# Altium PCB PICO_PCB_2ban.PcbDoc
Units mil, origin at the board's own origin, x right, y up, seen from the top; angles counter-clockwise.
Board outline 6000 x 4000 mil, 2 copper layers (Top Layer, Bottom Layer); 2 components, 20 nets, 86 pads, 1 vias.
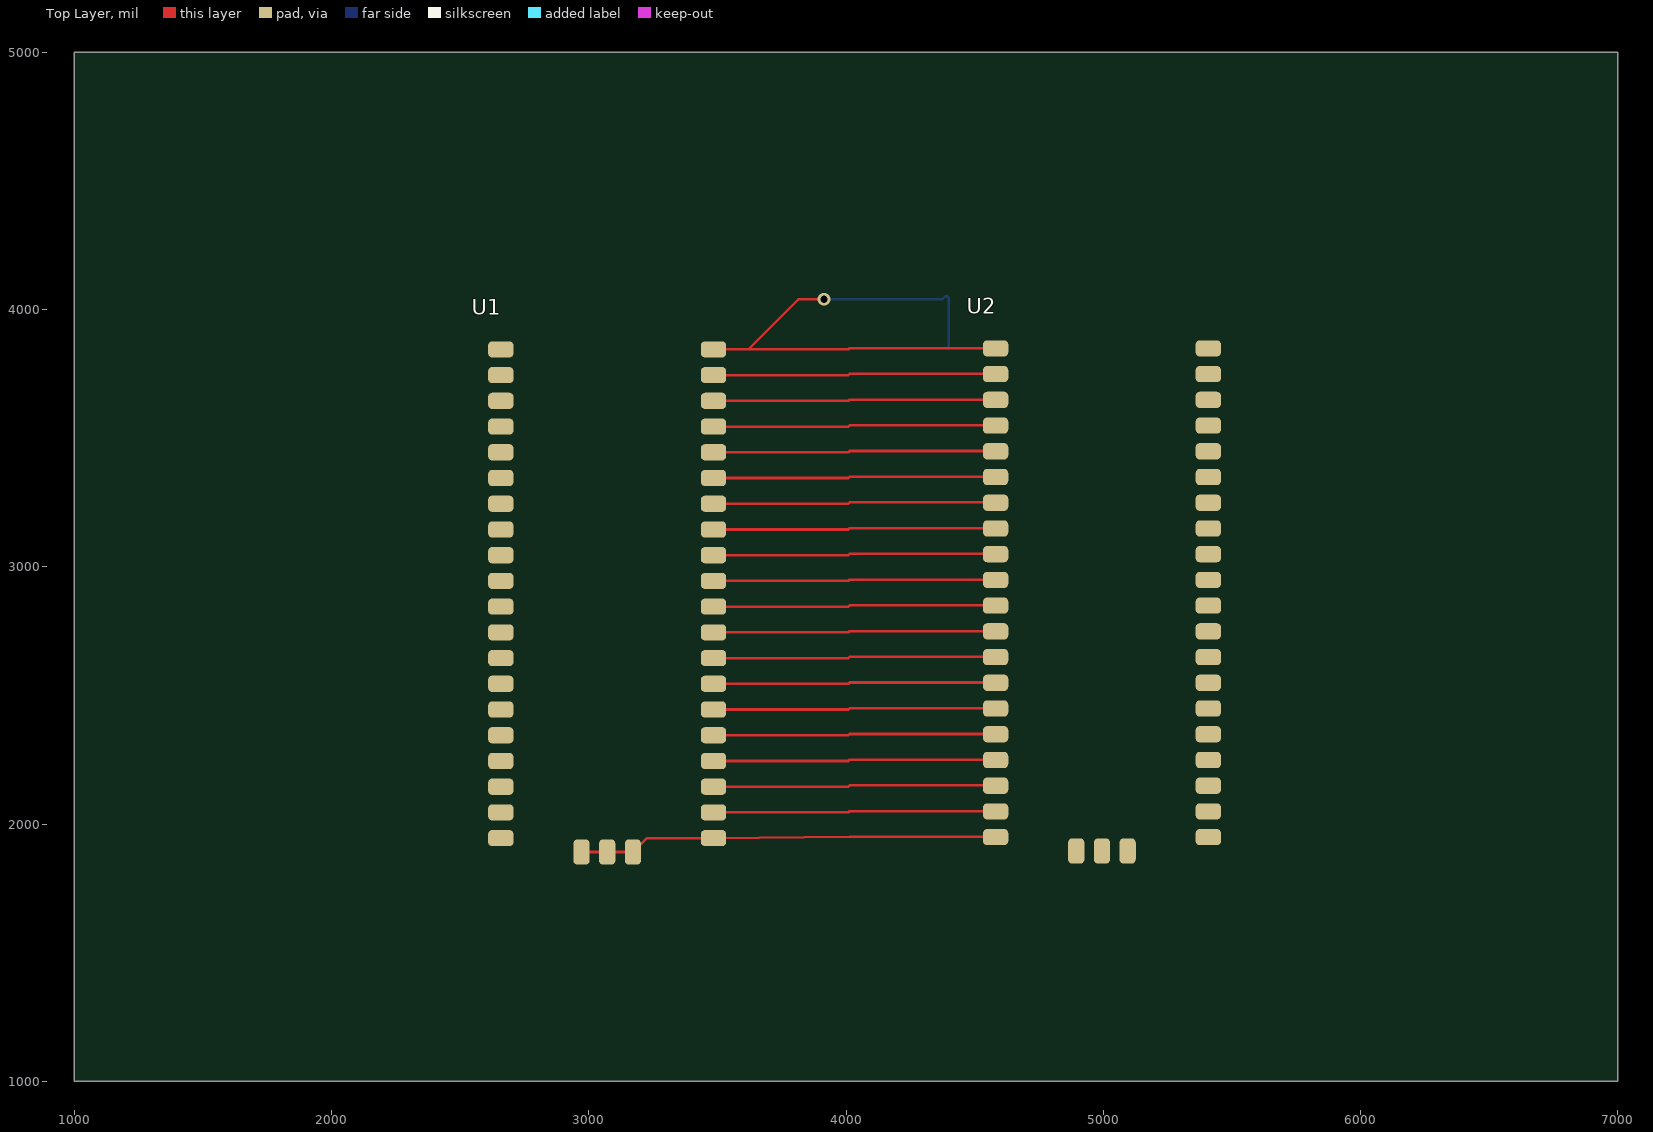
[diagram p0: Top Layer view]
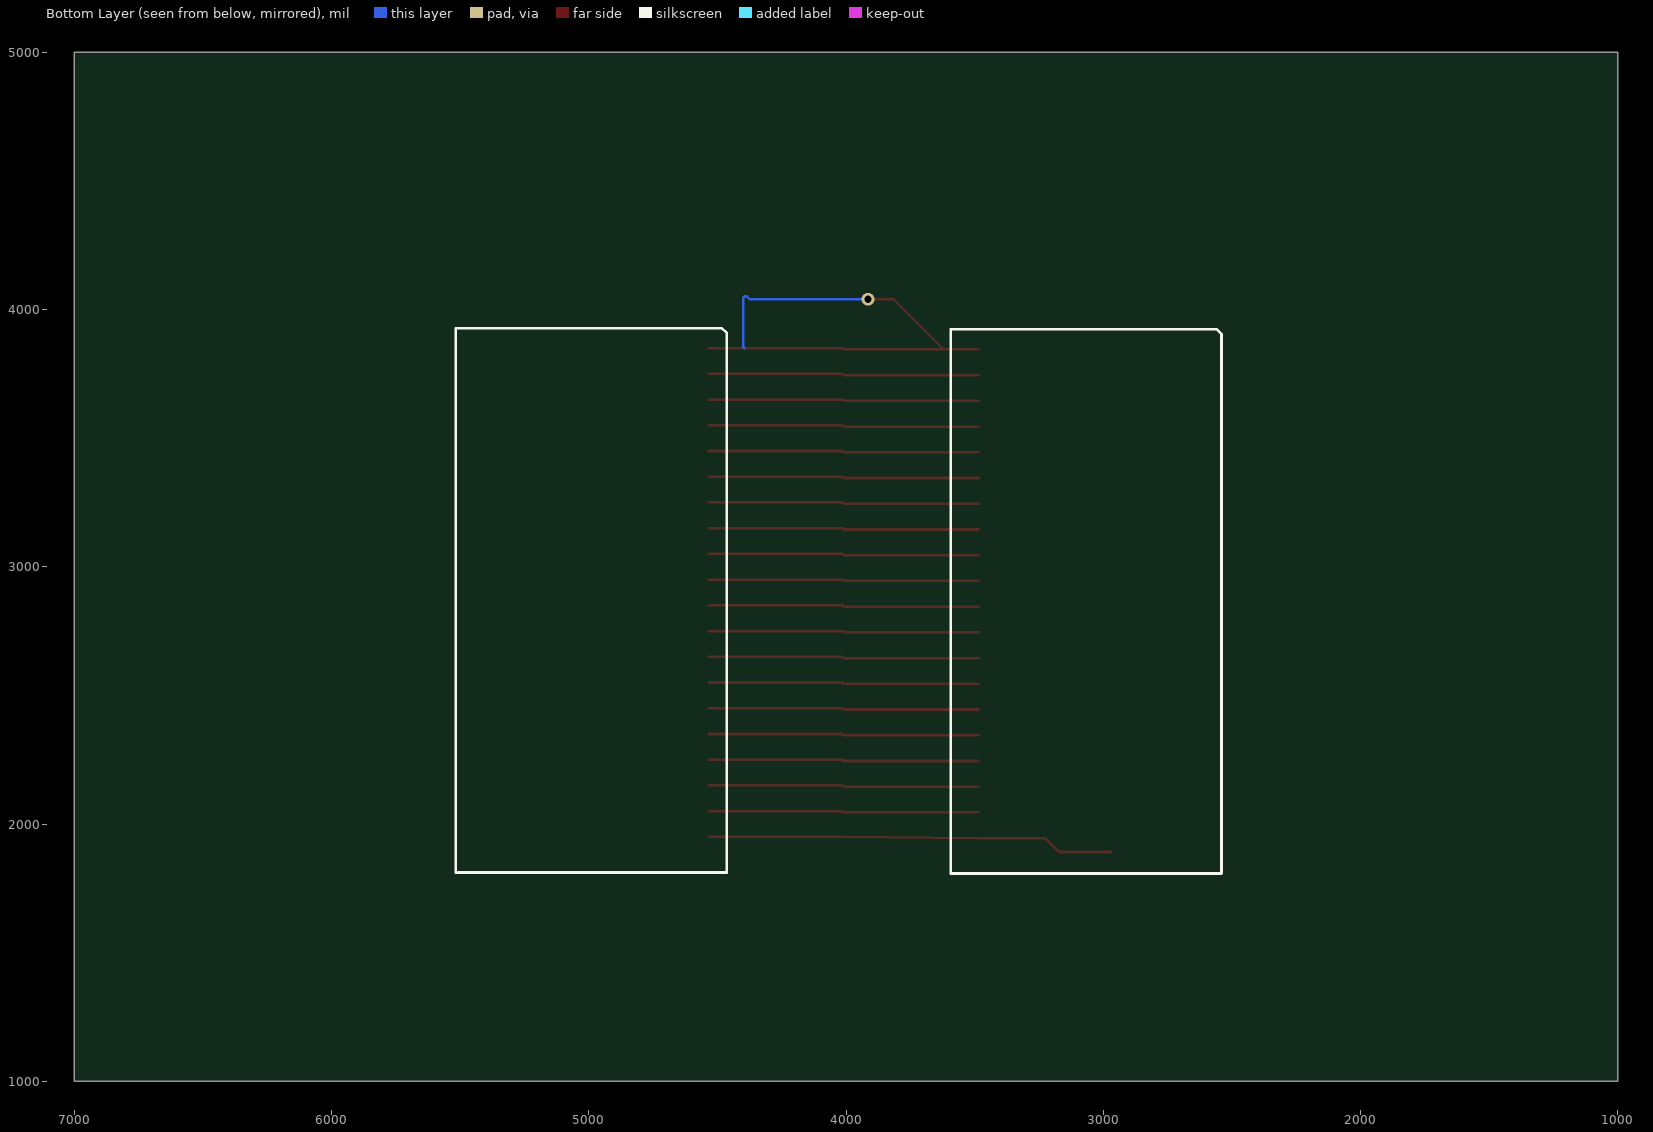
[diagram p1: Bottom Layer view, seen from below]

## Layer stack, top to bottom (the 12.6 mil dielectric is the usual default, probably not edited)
Top Solder: solder mask 0.4, Solder Resist, Dk 3.5
Top Layer: signal copper 1.4
Dielectric 1: dielectric 12.6, FR-4, Dk 4.8
Bottom Layer: signal copper 1.4
Bottom Solder: solder mask 0.4, Solder Resist, Dk 3.5

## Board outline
1000,1000 7000,1000 7000,5000 1000,5000

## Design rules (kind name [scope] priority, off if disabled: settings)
Clearance [All] p1: gap=10 ignorepadtopadclearanceinfootprint=FALSE except(0: Arc-Hole Track-Hole SMDPad-Hole THPad-Hole Via-Hole Fill-Hole Poly-Hole Region-Hole Text-Hole)
PolygonConnect [All] p1: connectstyle=Relief reliefconductorwidth=10 reliefentries=4 polygonreliefangle="90 Angle" airgapwidth=10
RoutingVias [All] p1: holewidth=28 width=50 viastyle="Through Hole" minholewidth=28 minwidth=50 maxholewidth=28 maxwidth=50
SolderMaskExpansion [All] p1: expansion=4 istentingtop=FALSE
Width [All] p1: maxlimit=10 minlimit=10 preferedwidth=10
30 further rules are at their usual default settings.

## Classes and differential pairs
component class MCU: U1

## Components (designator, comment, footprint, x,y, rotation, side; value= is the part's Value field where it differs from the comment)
U1 "RP2040" PCBComponent_1 2658.23,3845 r0 top
U2 "RP2040" PCBComponent_1 4581.61,3848.94 r0 top

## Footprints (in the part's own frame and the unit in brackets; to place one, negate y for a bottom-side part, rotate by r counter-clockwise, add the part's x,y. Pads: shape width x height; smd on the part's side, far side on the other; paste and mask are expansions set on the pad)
PCBComponent_1 [mm]
  rrect50% 2.5x1.6 smd: 1(0,0) 2(0,-2.54) 3(0,-5.08) 4(0,-7.62) 5(0,-10.16) 6(0,-12.7) 7(0,-15.24) 8(0,-17.78) 9(0,-20.32) 10(0,-22.86) 11(0,-25.4) 12(0,-27.94) 13(0,-30.48) 14(0,-33.02) 15(0,-35.56) 16(0,-38.1) 17(0,-40.64) 18(0,-43.18) 19(0,-45.72) 20(0,-48.26) 21(21,-48.26) 22(21,-45.72) 23(21,-43.18) 24(21,-40.64) 25(21,-38.1) 26(21,-35.56) 27(21,-33.02) 28(21,-30.48) 29(21,-27.94) 30(21,-25.4) 31(21,-22.86) 32(21,-20.32) 33(21,-17.78) 34(21,-15.24) 35(21,-12.7) 36(21,-10.16) 37(21,-7.62) 38(21,-5.08) 39(21,-2.54) 40(21,0)
  rrect50% 1.6x2.5 smd: 21(7.96,-49.63) 21(10.5,-49.63) 21(13.04,-49.63)
  body extent 0,-49.65 21,2.65, height 3.23

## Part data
U1 U2: library part Component_1

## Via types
v1: diameter 50, hole 28, Top Layer to Bottom Layer, 1 vias

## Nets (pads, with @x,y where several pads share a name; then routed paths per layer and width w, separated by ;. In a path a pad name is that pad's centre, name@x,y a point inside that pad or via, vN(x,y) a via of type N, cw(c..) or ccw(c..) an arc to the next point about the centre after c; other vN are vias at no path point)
NetU1_21: U1.21 U2.20 | length 1584
  Top Layer w10: U1.21@2971.61,1891.06 3071.61,1891.06 3171.61,1891.06 3225.55,1945 3485,1945 4014,1950 U2.20@4533.23,1950
NetU1_22: U1.22 U2.19 | length 1050.3
  Top Layer w10: U1.22 4009,2045 4014,2050 U2.19@4533.23,2050
NetU1_23: U1.23 U2.18 | length 1050.3
  Top Layer w10: U1.23 4009,2145 4014,2150 U2.18@4533.23,2150
NetU1_24: U1.24 U2.17 | length 1050.3
  Top Layer w10: U1.24 4009,2245 4014,2250 U2.17@4533.23,2250
NetU1_25: U1.25 U2.16 | length 1050.3
  Top Layer w10: U1.25 4009,2345 4014,2350 U2.16@4533.23,2350
NetU1_26: U1.26 U2.15 | length 1050.3
  Top Layer w10: U1.26 4009,2445 4014,2450 U2.15@4533.23,2450
NetU1_27: U1.27 U2.14 | length 1050.3
  Top Layer w10: U1.27 4009,2545 4014,2550 U2.14@4533.23,2550
NetU1_28: U1.28 U2.13 | length 1050.3
  Top Layer w10: U1.28 4009,2645 4014,2650 U2.13@4533.23,2650
NetU1_29: U1.29 U2.12 | length 1050.3
  Top Layer w10: U1.29 4009,2745 4014,2750 U2.12@4533.23,2750
NetU1_30: U1.30 U2.11 | length 1050.3
  Top Layer w10: U1.30 4009,2845 4014,2850 U2.11@4533.23,2850
NetU1_31: U1.31 U2.10 | length 1050.3
  Top Layer w10: U1.31 4009,2945 4014,2950 U2.10@4533.23,2950
NetU1_32: U1.32 U2.9 | length 1050.3
  Top Layer w10: U1.32 4009,3045 4014,3050 U2.9@4533.23,3050
NetU1_33: U1.33 U2.8 | length 1050.3
  Top Layer w10: U1.33 4009,3145 4014,3150 U2.8@4533.23,3150
NetU1_34: U1.34 U2.7 | length 1050.3
  Top Layer w10: U1.34 4009,3245 4014,3250 U2.7@4533.23,3250
NetU1_35: U1.35 U2.6 | length 1050.3
  Top Layer w10: U1.35 4009,3345 4014,3350 U2.6@4533.23,3350
NetU1_36: U1.36 U2.5 | length 1050.3
  Top Layer w10: U1.36 4009,3445 4014,3450 U2.5@4533.23,3450
NetU1_37: U1.37 U2.4 | length 1050.3
  Top Layer w10: U1.37 4009,3545 4014,3550 U2.4@4533.23,3550
NetU1_38: U1.38 U2.3 | length 1050.3
  Top Layer w10: U1.38 4009,3645 4014,3650 U2.3@4533.23,3650
NetU1_39: U1.39 U2.2 | length 1050.3
  Top Layer w10: U1.39 4009,3745 4014,3750 U2.2@4533.23,3750
VCC: U1.40 U2.1 | length 2115.1
  Top Layer w10: U1.40 3620,3845 ; v1(3915,4040) 3815,4040 3620,3845 ; U2.1@4533.23,3850 4014,3850 4009,3845 3620,3845
  Bottom Layer w10: v1(3915,4040) 4375,4040 4385.86,4050.86 4394.14,4050.86 4400,4045 4400,3855 4395,3850
pads on no net: U1.1 U1.2 U1.3 U1.4 U1.5 U1.6 U1.7 U1.8 U1.9 U1.10 U1.11 U1.12 U1.13 U1.14 U1.15 U1.16 U1.17 U1.18 U1.19 U1.20 U2.21 U2.22 U2.23 U2.24 U2.25 U2.26 U2.27 U2.28 U2.29 U2.30 U2.31 U2.32 U2.33 U2.34 U2.35 U2.36 U2.37 U2.38 U2.39 U2.40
